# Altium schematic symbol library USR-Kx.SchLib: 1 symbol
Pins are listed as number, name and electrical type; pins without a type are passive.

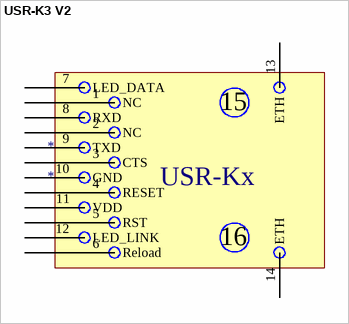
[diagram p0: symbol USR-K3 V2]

## USR-K3 V2
designator *
pins: 1 NC, 2 NC, 3 CTS, 4 RESET, 5 RST, 6 Reload, 7 LED_DATA, 8 RXD, 9 TXD, 10 GND, 11 VDD, 12 LED_LINK, 13 ETH, 14 ETH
